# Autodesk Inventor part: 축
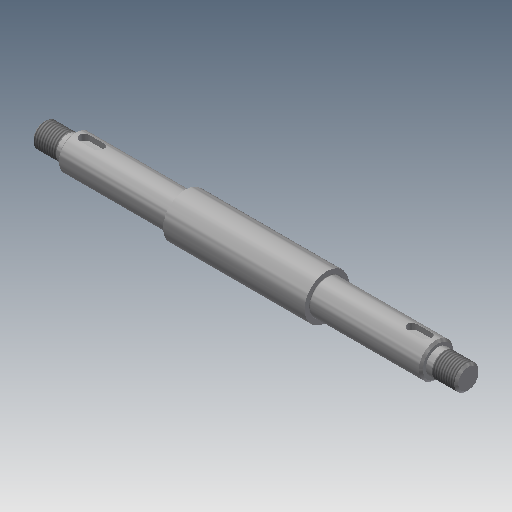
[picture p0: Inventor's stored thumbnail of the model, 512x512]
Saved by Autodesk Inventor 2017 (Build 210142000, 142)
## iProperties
Created: 2018-11
Part Number: 축
Material: 강철, 연강
Document SubType Name: Modeling
Designer: mduedu
Density: 1 g/cm^3
Appearance: Steel
Author: mduedu
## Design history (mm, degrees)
sketch "스케치1"
  geometry: L1 (-35, 0)-(35, 0); L2 (35, 0)-(35, 11); L3 (35, 11)-(-35, 11); L4 (-35, 11)-(-35, 0); L5 (-35, 0)-(-90, 0); L6 (-90, 0)-(-90, 8.5); L7 (-90, 8.5)-(-35, 8.5); L8 (-35, 8.5)-(-35, 0); L9 (-90, 0)-(-105, 0); L10 (-105, 0)-(-105, 6); L11 (-105, 6)-(-90, 6); L12 (-90, 6)-(-90, 0); L13 (0, 0)-(0, 11); L14 (35, 0)-(90, 0); L15 (90, 0)-(90, 8.5); L16 (90, 8.5)-(35, 8.5); L17 (35, 8.5)-(35, 0); L18 (90, 0)-(105, 0); L19 (105, 0)-(105, 6); L20 (105, 6)-(90, 6); L21 (90, 6)-(90, 0); 1 further point
  constraints: 42 end point, 6 parallel, 6 symmetric about line, 3 horizontal, 3 perpendicular, 2 midpoint, 1 coincident
  dimensions: "d0" = 22 diameter of L3 L1; "d2" = 17 diameter of L7 L5; "d3" = 12 diameter of L11 L9; "d4" = 70 distance of L2.end L3.end; "d5" = 55 distance of L6.end L7.end; "d6" = 210 distance between parallel lines of L19 L10
revolve "회전1" sketch "스케치1" stored, may be unused: angle "d7" = 90 deg
fillet "모깎기1" dims "d8" = 0.3
node "작업 평면1"
sketch "스케치2" dims "d11" = 12
  geometry: L1 (15, 2.5)-(22, 2.5); L2 (22, 2.5)-(22, -2.5); L3 (22, -2.5)-(15, -2.5); L4 (15, -2.5)-(15, 2.5); L5 (27.5, 8.5)-(27.5, -8.5) reference; 3 further points
  constraints: 8 end point, 2 midpoint, 2 parallel, 2 vertical alignment, 1 horizontal, 1 horizontal alignment, 1 perpendicular, 4 other
  dimensions: "d9" = 3 dimension on L5; "d10" = 5 distance between parallel lines of L3 L1
extrude "돌출1" cut sketch "스케치2" distance "d12" = 3; taper "d13" = 0 deg
chamfer "모따기1" distance "d14" = 1; stored, may be unused: second distance "d15" = 2, angle "d16" = 45 deg
feature "스레드1" dims "d17" = 12, "d18" = 0
feature "스레드2" dims "d19" = 12, "d20" = 0
chamfer "모따기2" distance "d21" = 1; stored, may be unused: second distance "d22" = 2, angle "d23" = 45 deg
node "솔리드1"
mirror "대칭1"
